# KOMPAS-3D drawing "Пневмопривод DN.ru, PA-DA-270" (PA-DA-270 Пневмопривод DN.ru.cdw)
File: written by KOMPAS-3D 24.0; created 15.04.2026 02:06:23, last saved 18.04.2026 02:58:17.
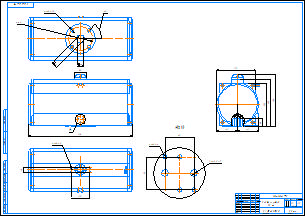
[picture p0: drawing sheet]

Document properties: Автор: DN.ru; Форматы листов документа: A1; Полное имя файла: PA-DA-270 Пневмопривод DN.ru.m3d; Масса: 97; Наименование: Пневмопривод DN.ru; Количество листов документа: 1; Примечание: D290-00301

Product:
- Part/product: Пневмопривод DN.ru  | designation PA-DA-270
    Масса: 97
    Раздел спецификации: Прочие изделия
    Примечание: D290-00301

Views: Вид 1, Вид:1, Проекционный вид 2, Проекционный вид 5, Местный разрез 1, Выносной элемент 6, Выносной элемент А, Выносной элемент
Referenced files in C:\Работа\PA-DA-х Пневмопривод DN.ru\052\: PA-DA-052 Пневмопривод DN.ru.m3d
Referenced files in C:\Работа\PA-DA-х Пневмопривод DN.ru\270\: PA-DA-270 Пневмопривод DN.ru.m3d
Referenced files in C:\Работа\PA-DA-х Пневмопривод DN.ru\160\: PA-DA-160 Пневмопривод DN.ru.m3d
Referenced files in C:\Program Files\ASCON\KOMPAS-3D v24\Templates\: Чертеж_DN.ru.cdt
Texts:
  objid
  viewid
  PA-DA-270
  Чертеж_DN.ru.cdt
  Пневмопривод
  Пневмопривод DN.ru
  PA-DA-270 Пневмопривод DN.ru
Dimensions and other numbers on the sheet: 0; 3; 2; 4; 80; 608; 718; 46; 165; 4 отв.; 20; 6; 273; 147; 299; 326; 356; 50; 7; 1; 2 отв.; 40; 45; 1:2,5; 97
